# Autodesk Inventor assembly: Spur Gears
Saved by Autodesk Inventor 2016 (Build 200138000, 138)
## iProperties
Created: 2016-10
Part Number: Spur Gears
Document SubType Name: Assembly
Designer: Ingenieria
Categories: <?xml version="1.0" encoding="UTF-16"?> <MemberInstance><Categories><FamilyTemplate/><ParamToTemplateMap><ParamToTemplate><ParamToTemplate CategoryParameter="//
ClientObjectVersion: 1
Author: Ingenieria
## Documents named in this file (2)
- C:\Users\ingenieria\Desktop\Project\Enfriador\Design Accelerator\Spur Gears1.iam
- C:\Users\ingenieria\Desktop\Project\Enfriador\Design Accelerator\Spur Gear21.ipt
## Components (1 placed, 1 different names)
1. Spur Gear2:1
